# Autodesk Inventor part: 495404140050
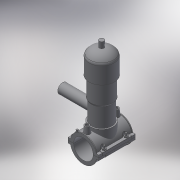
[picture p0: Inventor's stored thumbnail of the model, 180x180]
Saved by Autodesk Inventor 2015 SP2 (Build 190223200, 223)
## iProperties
Created: 2017-07
Part Number: 495404140050
Material: Generic
Description: PLASSON TAPPING VALVE 140-50
Document SubType Name: Modeling
Designer: KIM
Density: 1 g/cm^3
Appearance: Default
Author: KIM
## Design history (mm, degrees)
derived "495404-4954S4.ipt"
feature "Solid1::495404-4954S4.ipt"
feature "Solid2::495404-4954S4.ipt"
tag "TaggingFeature1"
body "Solid1"
body "Solid2"
other parameters: "d3" = 35, "d4" = 118, "d5" = 0, "d6" = 0.1, "d8" = 0, "d19" = 6, "d20" = 6, "d21" = 70.8, "d23" = 0, "d24" = 35.4, "d26" = 0, "d27" = 3, "d28" = 3, "d29" = 3, "d30" = 46.66667, "d31" = 6, "d32" = 0, "d33" = 0, "d34" = 0.6, "d40" = 87.36, "d47" = 135, "d70" = 15, "d72" = 0, "d73" = 6, "d75" = 5, "d76" = 0, "d77" = 7, "d79" = 15, "d80" = 47.2, "d82" = 5 deg, "d84" = 4, "d85" = 14, "d86" = 0, "d87" = 3, "d88" = 0, "d89" = 1, "d90" = 1, "d91" = 94.4, "d92" = 0, "d93" = 0.5, "d94" = 73.68421, "d96" = 173.04, "d97" = 2.36, "d98" = 0, "d120" = 140 deg, "d121" = 24.228, "d122" = 20 deg, "d123" = 336, "d124" = 100.8, "d126" = 0, "d143" = 144.2, "d145" = 21.53846, "d149" = 2.1, "d150" = 23.69231, "d153" = 118, "d154" = 0, "d156" = 84, "d157" = 160 deg, "d159" = 5.6, "d161" = 2.1, "d162" = 70.8, "d163" = 0, "d167" = 14, "d168" = 81.95122, "d170" = 3, "d172" = 0, "d173" = 1, "d176" = 20 deg, "d177" = 9.8, "d178" = 28, "d180" = 0, "d183" = 11.2, "d184" = 7.84, "d185" = 38.35, "d186" = 38.35, "d187" = 84, "d188" = 8.4, "d189" = 9.8, "d190" = 0, "d191" = 126, "d193" = 6.8, "d194" = 2.95, "d195" = 90 deg, "d197" = 0, "d199" = 0, "d205" = 14.64, "d206" = 81.33333, "d207" = 244, "d208" = 224.48, "d209" = 207.4, "d210" = 200.08, "d211" = 146.4, "d212" = 85.4, "d213" = 65.88, "d214" = 73.2, "d216" = 19.52, "d217" = 70.76, "d218" = 80.52, "d222" = 0, "d223" = 168, "d224" = 152, "d225" = 51, "d229" = 152, "d230" = 0, "H_" = 152, "L_" = 118, "d_t" = 6, "H_1" = 51, "H_2" = 244, "d148" = 2.1, "d160" = 2.1, "d169" = 3, "d192" = 6.8
